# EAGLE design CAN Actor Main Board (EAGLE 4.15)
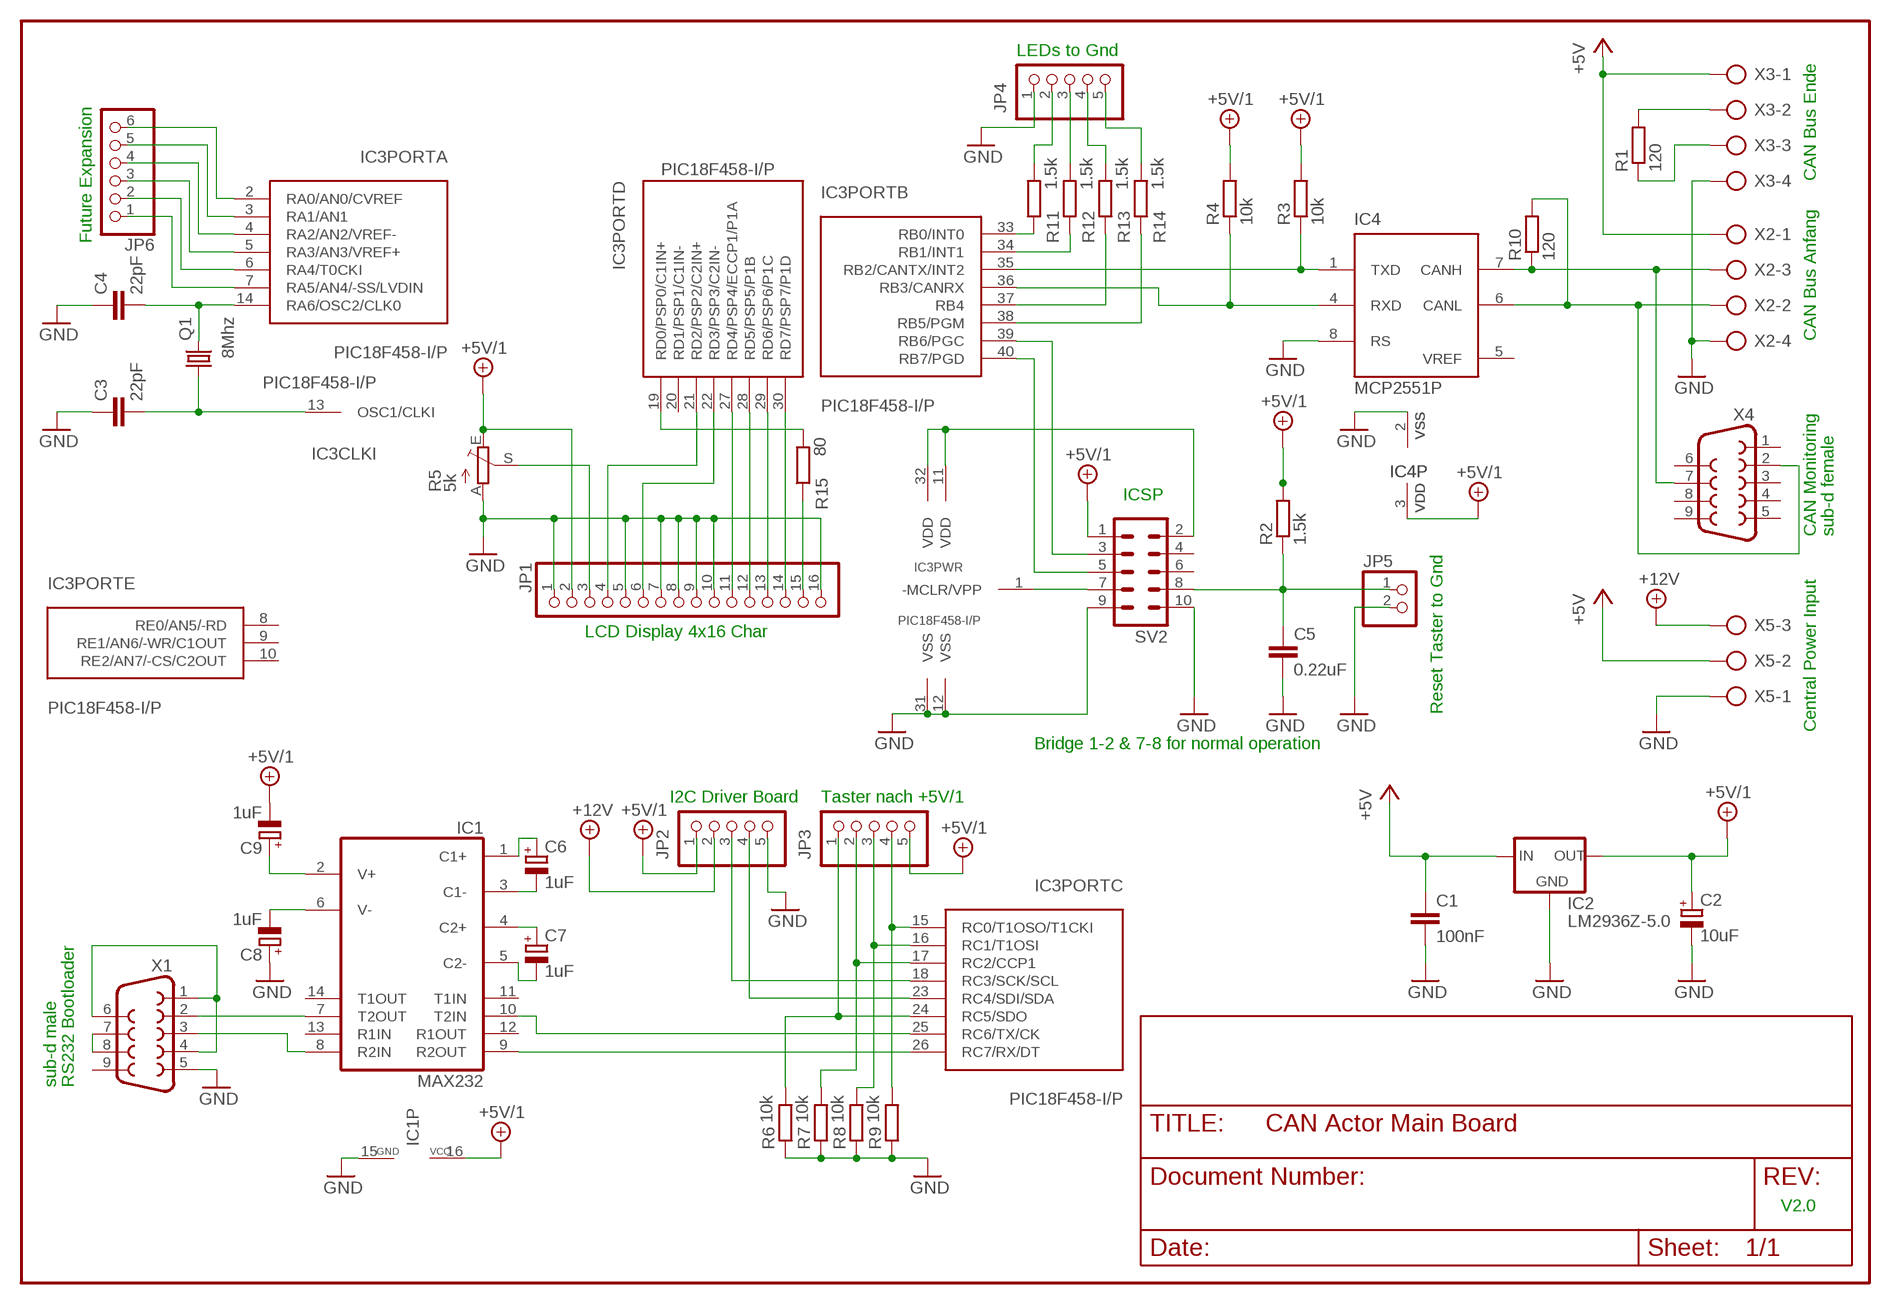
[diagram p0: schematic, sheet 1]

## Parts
C1  100nF  C2.5/2  [C2.5-2]
C2  10uF  CPOL-EUB45181A  [B45181A]
C3  22pF  C-EU025-025X050  [C025-025X050]
C4  22pF  C-EU025-025X050  [C025-025X050]
C5  0.22uF  C-EU025-025X050  [C025-025X050]
C6  1uF  CPOL-EUB45181A  [B45181A]
C7  1uF  CPOL-EUB45181A  [B45181A]
C8  1uF  CPOL-EUB45181A  [B45181A]
C9  1uF  CPOL-EUB45181A  [B45181A]
IC1  MAX232  [DIL16]
IC2  LM2936Z-5.0  78LXX  [78LXX]
IC3  PIC18F458-I/P  [DIL40]
IC4  MCP2551P  [DIL8]
JP1  PINHD-1X16  [1X16]
JP2  PINHD-1X5  [1X05]
JP3  PINHD-1X5  [1X05]
JP4  PINHD-1X5  [1X05]
JP5  PINHD-1X2  [1X02]
JP6  PINHD-1X6  [1X06]
Q1  8Mhz  CRYTALHC49S  [HC49/S]
R1  120  R-EU_0204/7  [0204/7]
R2  1.5k  R-EU_0204/7  [0204/7]
R3  10k  R-EU_0204/7  [0204/7]
R4  10k  R-EU_0204/7  [0204/7]
R5  5k  TRIM_EU-LI10  [LI10]
R6  10k  R-EU_0204/7  [0204/7]
R7  10k  R-EU_0204/7  [0204/7]
R8  10k  R-EU_0204/7  [0204/7]
R9  10k  R-EU_0204/7  [0204/7]
R10  120  R-EU_0204/7  [0204/7]
R11  1.5k  R-EU_0204/7  [0204/7]
R12  1.5k  R-EU_0204/7  [0204/7]
R13  1.5k  R-EU_0204/7  [0204/7]
R14  1.5k  R-EU_0204/7  [0204/7]
R15  80  R-EU_0204/7  [0204/7]
SV2  ML10  [ML10]
X1  F09VB  [F09VB]
X2  AK500/4  [AK500/4]
X3  AK500/4  [AK500/4]
X4  F09VB  [F09VB]
X5  AK500/3  [AK500/3]

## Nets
+5V: C1.1 IC2.IN X2.1 X3.1 X5.2
+5V/1: C2.+ C9.- IC1.16(VCC) IC2.OUT IC4.3(VDD) JP1.2 JP2.1 JP3.5 R2.2 R3.2 R4.2 R5.E SV2.1
+12V: JP2.2 X5.3
GND: C1.2 C2.- C3.1 C4.1 C5.2 C8.+ IC1.15(GND) IC2.GND IC3.12(PWR:VSS) IC3.31(PWR:VSS) IC4.2(VSS) IC4.8(RS) JP1.1 JP1.5 JP1.7 JP1.8 JP1.9 JP1.10 JP1.16 JP2.5 JP4.1 JP5.2 R5.A R6.1 R7.1 R8.1 R9.1 SV2.9 SV2.10 X1.5 X2.4 X3.4 X5.1
N$1: IC3.35(PORTB:RB2/CANTX/INT2) IC4.1(TXD) R3.1
N$2: IC3.36(PORTB:RB3/CANRX) IC4.4(RXD) R4.1
N$3: IC4.7(CANH) R10.1 X2.3 X4.7
N$4: C3.2 IC3.13(CLKI:OSC1/CLKI) Q1.1
N$5: IC4.6(CANL) R10.2 X2.2 X4.2
N$6: IC3.1(PWR:-MCLR/VPP) SV2.7
N$7: IC3.11(PWR:VDD) IC3.32(PWR:VDD) SV2.2
N$8: IC3.39(PORTB:RB6/PGC) SV2.3
N$9: C4.2 IC3.14(PORTA:RA6/OSC2/CLK0) Q1.2
N$10: IC3.33(PORTB:RB0/INT0) R11.1
N$11: IC3.34(PORTB:RB1/INT1) R12.1
N$12: IC3.40(PORTB:RB7/PGD) SV2.5
N$13: IC3.27(PORTD:RD4/PSP4/ECCP1/P1A) JP1.11
N$14: C5.1 JP5.1 R2.1 SV2.8
N$15: IC3.22(PORTD:RD3/PSP3/C2IN-) JP1.6
N$16: JP1.3 R5.S
N$17: IC3.21(PORTD:RD2/PSP2/C2IN+) JP1.4
N$18: IC3.30(PORTD:RD7/PSP7/P1D) JP1.14
N$19: IC3.29(PORTD:RD6/PSP6/P1C) JP1.13
N$20: IC3.28(PORTD:RD5/PSP5/P1B) JP1.12
N$21: IC1.10(T2IN) IC3.25(PORTC:RC6/TX/CK)
N$22: IC1.9(R2OUT) IC3.26(PORTC:RC7/RX/DT)
N$23: C6.- IC1.3(C1-)
N$24: C6.+ IC1.1(C1+)
N$25: C7.+ IC1.4(C2+)
N$26: C7.- IC1.5(C2-)
N$27: C8.- IC1.6(V-)
N$28: C9.+ IC1.2(V+)
N$29: IC1.7(T2OUT) X1.2
N$30: IC1.8(R2IN) X1.3
N$31: X1.7 X1.8
N$32: X1.1 X1.4 X1.6
N$33: IC3.18(PORTC:RC3/SCK/SCL) JP2.3
N$34: IC3.23(PORTC:RC4/SDI/SDA) JP2.4
N$35: IC3.15(PORTC:RC0/T1OSO/T1CKI) JP3.4 R9.2
N$36: IC3.16(PORTC:RC1/T1OSI) JP3.3 R8.2
N$37: IC3.17(PORTC:RC2/CCP1) JP3.2 R7.2
N$38: IC3.24(PORTC:RC5/SDO) JP3.1 R6.2
N$39: IC3.37(PORTB:RB4) R13.1
N$40: R1.2 X3.2
N$41: R1.1 X3.3
N$42: IC3.38(PORTB:RB5/PGM) R14.1
N$43: JP4.2 R11.2
N$44: JP4.3 R12.2
N$45: JP4.4 R13.2
N$46: JP4.5 R14.2
N$48: JP1.15 R15.1
N$49: IC3.19(PORTD:RD0/PSP0/C1IN+) R15.2
N$50: IC3.7(PORTA:RA5/AN4/-SS/LVDIN) JP6.1
N$51: IC3.6(PORTA:RA4/T0CKI) JP6.2
N$52: IC3.5(PORTA:RA3/AN3/VREF+) JP6.3
N$53: IC3.4(PORTA:RA2/AN2/VREF-) JP6.4
N$54: IC3.3(PORTA:RA1/AN1) JP6.5
N$55: IC3.2(PORTA:RA0/AN0/CVREF) JP6.6
Unconnected: IC1.11(T1IN) IC1.12(R1OUT) IC1.13(R1IN) IC1.14(T1OUT) IC3.8(PORTE:RE0/AN5/-RD) IC3.9(PORTE:RE1/AN6/-WR/C1OUT) IC3.10(PORTE:RE2/AN7/-CS/C2OUT) IC3.20(PORTD:RD1/PSP1/C1IN-) SV2.4 SV2.6 X1.9 X4.1 X4.3 X4.4 X4.5 X4.6 X4.8 X4.9

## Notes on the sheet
- LEDs to Gnd
- CAN Bus Ende
- Future Expansion
- CAN Bus Anfang
- ICSP
- CAN Monitoring | sub-d female
- LCD Display 4x16 Char
- Reset Taster to Gnd
- Central Power Input
- Bridge 1-2 & 7-8 for normal operation
- I2C Driver Board | Taster nach +5V/1
- sub-d male | RS232 Bootloader
- V2.0

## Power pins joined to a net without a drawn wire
VREF: IC4.5(VREF)

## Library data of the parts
C1 = capacitor-wima:C: CAPACITOR
C2 C6-C9 = rcl:CPOL-EU: POLARIZED CAPACITOR, European symbol
C3-C5 = rcl:C-EU: CAPACITOR, European symbol
IC1 = maxim:MAX232: RS232 TRANSEIVER
IC2 = v-reg:78LXX: VOLTAGE REGULATOR
IC3 = pic18fxx20-fxx8:PIC18F4*8: 40-Pin High Performance, Enhanced FLASH Microcontrollers with CAN device program memory (bytes) data RAM (bytes) PIC18F44816K768 PIC18F45832K1536
IC4 = microchip_can:MCP2551: High Speed CAN tranceiver
JP1 = pinhead:PINHD-1X16: PIN HEADER
JP2-JP4 = pinhead:PINHD-1X5: PIN HEADER
JP5 = pinhead:PINHD-1X2: PIN HEADER
JP6 = pinhead:PINHD-1X6: PIN HEADER
Q1 = crystal:CRYTAL: CRYSTAL
R1-R4 R6-R15 = rcl:R-EU_: RESISTOR, European symbol
R5 = pot:TRIM_EU-: POTENTIOMETER
SV2 = con-harting-ml:ML10: HARTING
X1 X4 = con-subd:F09: SUB-D
X2 X3 = con-ptr500:AK500/4: CONNECTOR
X5 = con-ptr500:AK500/3: CONNECTOR

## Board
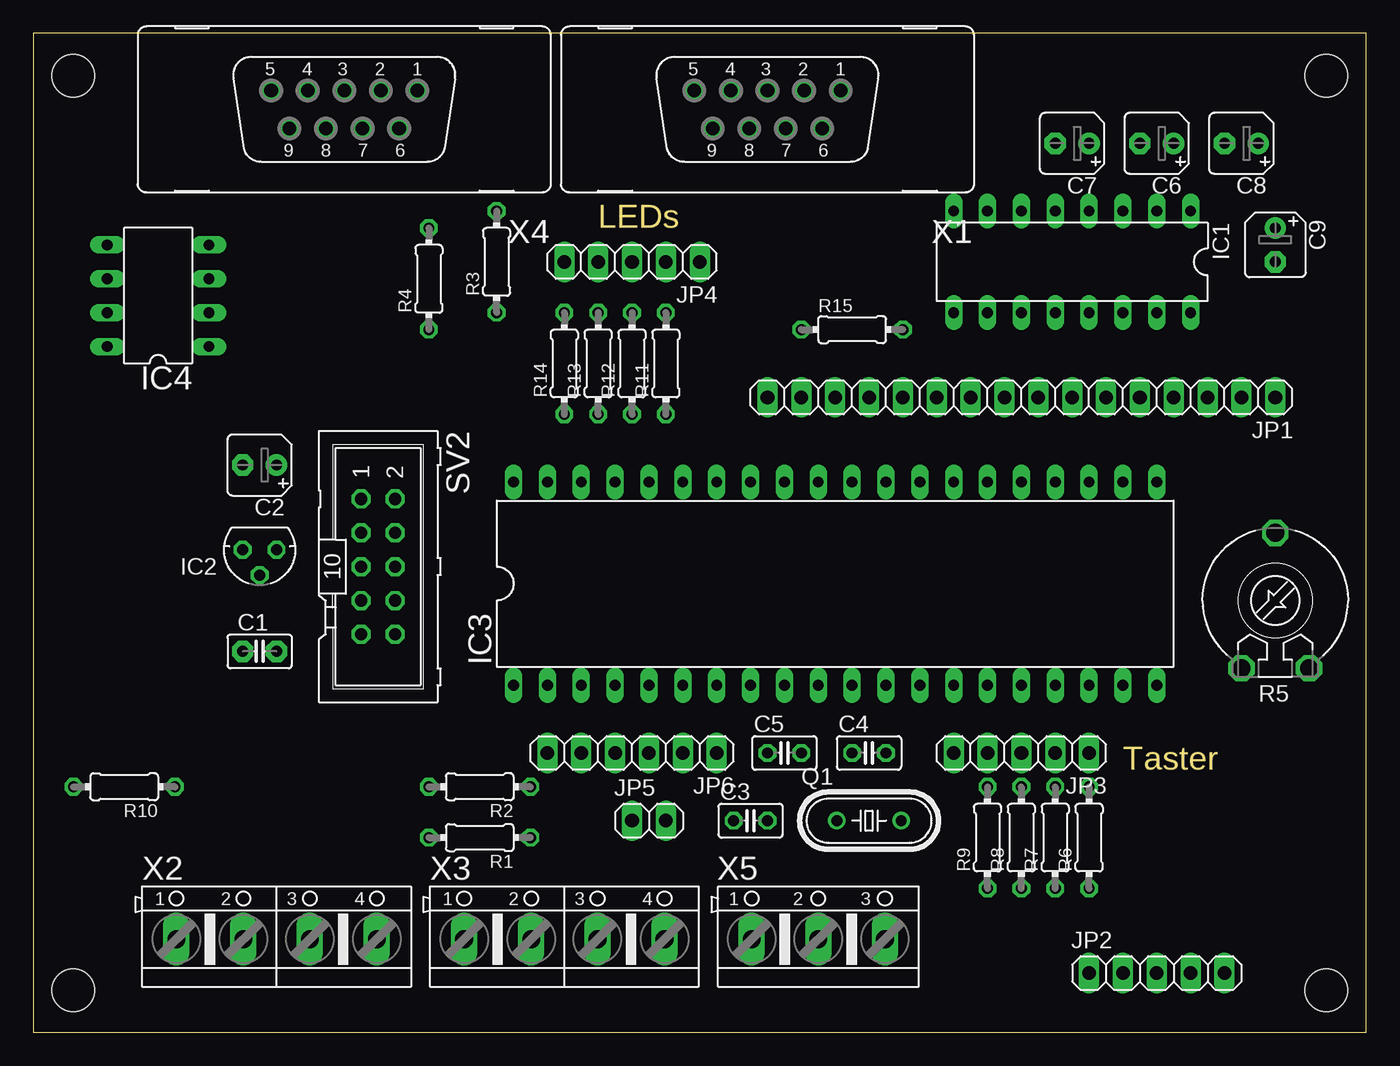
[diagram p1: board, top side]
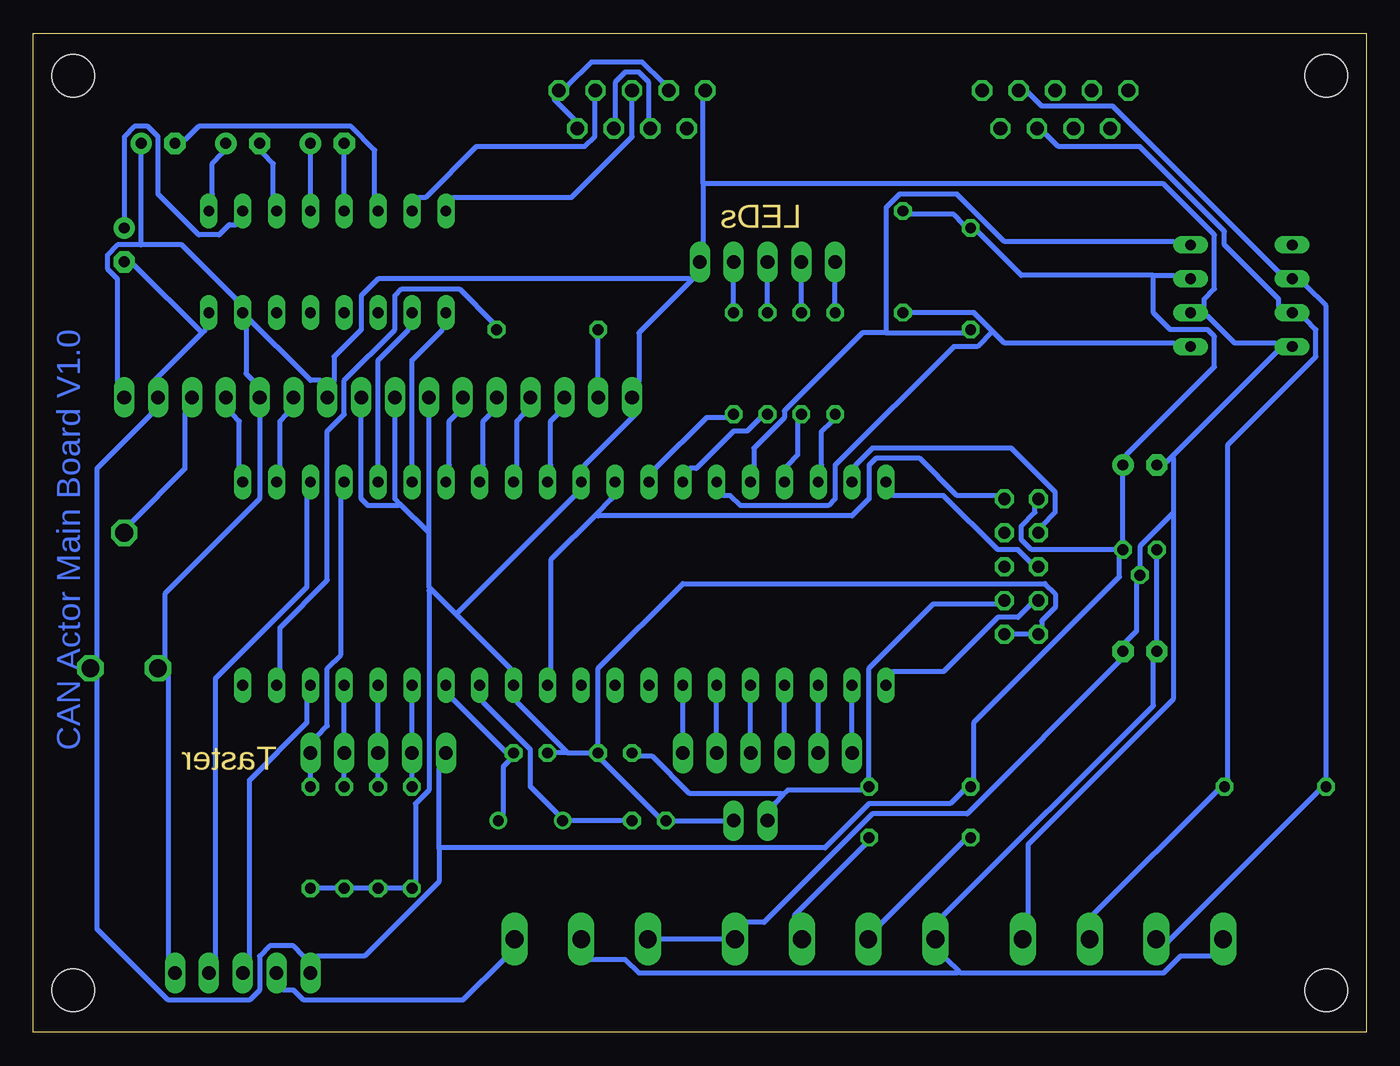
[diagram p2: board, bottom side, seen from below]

Size 100 x 74.92 mm. Coordinates in mm from the lower left corner, seen from the top.
Outline: 0,0 100,0 100,74.92 0,74.92 0,0
Copper layers (1*16): Top 0.035mm / dielectric 1.5mm / Bottom 0.035mm
Design rules "default": minimum track width 15mil, minimum drill 24mil, track to track 8mil, track to pad 8mil, pad to pad 8mil, via to via 8mil, smd to smd 8mil, copper to edge 40mil, drill to drill 8mil, minimum pad ring 10mil, minimum via ring 8mil, stop-mask expansion 4mil, vias tented up to drill 0mil, thermal gap 10mil
Holes 3.2 mm at 3.01,3.17 3.01,71.75 96.99,71.75 96.99,3.17

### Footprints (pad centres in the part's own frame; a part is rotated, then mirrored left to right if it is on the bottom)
C2.5-2 = drill 0.813 pad 1.6 octagon: 1 -1.27,0; 2 1.27,0
B45181A = drill 0.813 pad 1.6 round: + -1.27,0 | drill 0.813 pad 1.6 octagon: - 1.27,0
C025-025X050 = drill 0.813 octagon: 1 -1.27,0; 2 1.27,0
DIL16 = drill 0.813 long: 1 -8.89,-3.81; 2 -6.35,-3.81; 3 -3.81,-3.81; 4 -1.27,-3.81; 5 1.27,-3.81; 6 3.81,-3.81; 7 6.35,-3.81; 8 8.89,-3.81; 9 8.89,3.81; 10 6.35,3.81; 11 3.81,3.81; 12 1.27,3.81; 13 -1.27,3.81; 14 -3.81,3.81; 15 -6.35,3.81; 16 -8.89,3.81
78LXX = drill 0.813 octagon: GND 0,1.905; IN 1.27,0; OUT -1.27,0
DIL40 = drill 0.813 long: 1 -24.13,-7.62; 2 -21.59,-7.62; 3 -19.05,-7.62; 4 -16.51,-7.62; 5 -13.97,-7.62; 6 -11.43,-7.62; 7 -8.89,-7.62; 8 -6.35,-7.62; 9 -3.81,-7.62; 10 -1.27,-7.62; 11 1.27,-7.62; 12 3.81,-7.62; 13 6.35,-7.62; 14 8.89,-7.62; 15 11.43,-7.62; 16 13.97,-7.62; 17 16.51,-7.62; 18 19.05,-7.62; 19 21.59,-7.62; 20 24.13,-7.62; 21 24.13,7.62; 22 21.59,7.62; 23 19.05,7.62; 24 16.51,7.62; 25 13.97,7.62; 26 11.43,7.62; 27 8.89,7.62; 28 6.35,7.62; 29 3.81,7.62; 30 1.27,7.62; 31 -1.27,7.62; 32 -3.81,7.62; 33 -6.35,7.62; 34 -8.89,7.62; 35 -11.43,7.62; 36 -13.97,7.62; 37 -16.51,7.62; 38 -19.05,7.62; 39 -21.59,7.62; 40 -24.13,7.62
DIL8 = drill 0.813 long: 1 -3.81,-3.81; 2 -1.27,-3.81; 3 1.27,-3.81; 4 3.81,-3.81; 5 3.81,3.81; 6 1.27,3.81; 7 -1.27,3.81; 8 -3.81,3.81
1X16 = drill 1.016 long: 1 -19.05,0; 2 -16.51,0; 3 -13.97,0; 4 -11.43,0; 5 -8.89,0; 6 -6.35,0; 7 -3.81,0; 8 -1.27,0; 9 1.27,0; 10 3.81,0; 11 6.35,0; 12 8.89,0; 13 11.43,0; 14 13.97,0; 15 16.51,0; 16 19.05,0
1X05 = drill 1.016 long: 1 -5.08,0; 2 -2.54,0; 3 0,0; 4 2.54,0; 5 5.08,0
1X02 = drill 1.016 long: 1 -1.27,0; 2 1.27,0
1X06 = drill 1.016 long: 1 -6.35,0; 2 -3.81,0; 3 -1.27,0; 4 1.27,0; 5 3.81,0; 6 6.35,0
HC49/S = drill 0.813 round: 1 -2.413,0; 2 2.413,0
0204/7 = drill 0.813 octagon: 1 -3.81,0; 2 3.81,0
LI10 = drill 1.321 octagon: A -2.54,-5.08; E 2.54,-5.08; S 0,5.08
ML10 = drill 0.914 octagon: 1 -5.08,-1.27; 2 -5.08,1.27; 3 -2.54,-1.27; 4 -2.54,1.27; 5 0,-1.27; 6 0,1.27; 7 2.54,-1.27; 8 2.54,1.27; 9 5.08,-1.27; 10 5.08,1.27
F09VB = drill 1.016 octagon: 1 -5.486,-1.422; 2 -2.743,-1.422; 3 0,-1.422; 4 2.743,-1.422; 5 5.486,-1.422; 6 -4.115,1.422; 7 -1.372,1.422; 8 1.372,1.422; 9 4.115,1.422
AK500/4 = drill 1.321 long: 1 -7.518,0; 2 -2.489,0; 3 2.489,0; 4 7.518,0
AK500/3 = drill 1.321 long: 1 -5.004,0; 2 0,0; 3 5.004,0

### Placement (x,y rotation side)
C1  16.98,28.57 0 top
C2  16.98,42.54 180 top
C3  53.81,15.87 0 top
C4  62.7,20.95 0 top
C5  56.35,20.95 0 top
C6  84.29,66.67 180 top
C7  77.94,66.67 180 top
C8  90.64,66.67 180 top
C9  93.18,59.05 270 top
IC1  77.94,57.78 180 top
IC2  16.98,36.19 180 top
IC3  60.16,33.65 0 top
IC4  9.36,55.24 90 top
JP1  74.13,47.62 180 top
JP2  84.29,4.44 0 top
JP3  74.13,20.95 180 top
JP4  44.92,57.78 180 top
JP5  46.19,15.87 0 top
JP6  44.92,20.95 180 top
Q1  62.7,15.87 0 top
R1  33.49,14.6 180 top
R2  33.49,18.41 180 top
R3  34.76,57.78 90 top
R4  29.68,56.51 90 top
R5  93.18,32.38 0 top
R6  79.21,14.6 90 top
R7  76.67,14.6 90 top
R8  74.13,14.6 90 top
R9  71.59,14.6 90 top
R10  6.82,18.41 180 top
R11  47.46,50.16 90 top
R12  44.92,50.16 90 top
R13  42.38,50.16 90 top
R14  39.84,50.16 90 top
R15  61.43,52.7 0 top
SV2  25.87,34.92 270 top
X1  55.08,69.21 180 top
X2  18.25,6.98 0 top
X3  39.84,6.98 0 top
X4  23.33,69.21 180 top
X5  58.89,6.98 0 top

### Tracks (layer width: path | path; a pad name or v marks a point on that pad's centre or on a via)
+5V
  Bottom 0.381: IC2.IN C1.1 15.96,27.81 15.96,24.51 31.71,8.76 X3.1 31.46,5.46 30.57,4.57 | 30.57,4.57 30.44,4.44 15.2,4.44 13.93,5.71 11.65,5.71 X2.1 | X5.2 58.13,5.46 55.59,5.46 54.57,4.44 30.7,4.44 30.57,4.57
+5V/1
  Bottom 0.381: 87.34,52.45 90.89,48.89 JP1.2 91.15,46.35 95.21,42.29 95.21,28.06 R5.E 95.21,26.54 95.21,7.74 89.88,2.41 83.78,2.41 83.02,3.17 83.02,5.71 82.26,6.47 80.48,6.47 79.72,5.71 JP2.1 78.7,5.71 75.15,5.71 69.56,11.3 69.56,13.84 | 87.34,52.45 87.08,52.7 IC1.16 | 87.34,52.45 92.42,57.53 C9.- | 69.56,13.84 69.56,19.68 JP3.5 | 15.96,56.76 25.87,56.76 29.17,60.07 R4.2 30.19,60.57 30.95,61.34 34.25,61.34 R3.2 | 15.96,56.76 14.44,56.76 IC4.3 | IC2.OUT C2.+ 18,43.3 11.39,49.91 11.39,52.19 11.9,52.7 14.69,52.7 15.96,53.97 15.96,56.76 | IC2.OUT 18.5,35.68 18.5,34.16 29.43,23.24 29.43,18.92 R2.2 30.19,18.16 31.2,17.14 37.3,17.14 40.6,13.84 69.56,13.84 | SV2.1 24.85,39.49 24.85,38.98 25.87,37.97 25.87,36.95 25.11,36.19 IC2.OUT
+12V
  Bottom 0.381: JP2.2 81.24,3.17 80.48,3.17 79.72,2.41 67.78,2.41 64.73,5.46 X5.3
GND
  Bottom 0.381: X5.1 X3.4 46.44,8.25 45.17,8.25 37.05,16.38 29.93,16.38 18.5,27.81 C1.2 18,29.33 17.23,30.09 17.23,33.65 IC2.GND 16.98,36.44 14.44,38.98 | 14.57,43.17 6.57,51.18 IC4.8 6.82,51.68 9.87,51.68 11.9,53.72 IC4.2 12.15,54.48 12.15,54.99 11.39,55.75 11.39,59.81 15.2,63.62 49.75,63.62 | 14.57,43.17 14.95,42.79 C2.- | 14.44,38.98 14.44,43.05 14.57,43.17 | 14.44,38.98 14.44,25.01 25.36,14.09 25.36,8.76 X2.4 | JP2.5 89.88,5.71 89.88,26.79 R5.A 90.13,28.06 90.13,32.89 83.02,40 JP1.5 83.53,48.89 84.04,49.4 84.04,52.7 IC1.15 | IC1.15 79.21,48.89 78.45,48.89 JP1.7 77.43,48.89 77.43,50.67 75.4,52.7 75.4,55.24 74.13,56.51 50.76,56.51 50.63,56.38 | 91.91,59.05 88.86,59.05 84.8,54.99 IC1.15 | 91.91,59.05 93.69,59.05 94.45,58.29 94.45,57.27 93.69,56.51 93.69,48.89 JP1.1 | 91.91,59.05 C8.+ | 49.75,63.62 49.75,69.97 X1.5 | 49.75,63.62 49.75,59.05 JP4.1 50.51,56.51 50.63,56.38 | 50.63,56.38 54.57,52.45 54.57,48.89 JP1.16 54.83,46.35 58.64,42.54 IC3.31 59.4,40.25 68.29,31.36 | R6.1 R7.1 R8.1 R9.1 71.34,11.3 71.34,17.14 70.32,18.16 70.32,33.14 70.19,33.27 | JP5.2 C3.1 53.05,16.12 57.37,20.44 C5.2 | SV2.10 SV2.9 24.35,30.35 24.35,30.86 23.33,31.87 23.33,32.89 24.09,33.65 51.27,33.65 57.62,27.3 C5.2 | 59.91,20.95 C5.2 | 59.91,20.95 C4.1 | 59.91,20.95 63.72,24.76 IC3.12 64.22,27.3 68.29,31.36 | 70.32,37.46 70.32,33.4 70.19,33.27 | 68.29,31.36 70.19,33.27 | 70.32,37.46 JP1.10 | 70.32,37.46 72.48,39.62 | 72.48,39.62 72.86,40 JP1.9 | JP1.8 75.4,40 74.89,39.49 72.61,39.49 72.48,39.62
N$1
  Bottom 0.381: 28.03,52.57 29.43,53.97 R3.1 | 28.03,52.57 27.14,51.68 14.44,51.68 IC4.1 | IC3.35 48.22,40.25 47.71,40.25 46.95,39.49 40.35,39.49 39.84,40 39.84,42.54 30.95,51.43 29.17,51.43 28.03,52.57
N$2
  Bottom 0.381: 36.03,52.45 30.19,52.45 R4.1 | 36.03,52.45 37.81,52.45 43.65,46.6 43.65,46.1 45.94,43.81 45.94,42.54 IC3.36 | 36.03,52.45 36.03,61.84 35.01,62.86 30.7,62.86 27.14,59.3 14.44,59.3 IC4.4
N$3
  Bottom 0.381: X2.3 20.54,8.76 11.14,18.16 R10.1 10.38,18.92 10.38,44.06 3.77,50.67 3.77,52.7 4.53,53.46 IC4.7 6.57,54.48 6.57,54.99 10.63,59.05 10.63,60.07 16.98,66.42 23.08,66.42 24.09,67.43 X4.7
N$4
  Bottom 0.381: C3.2 Q1.1 60.67,16.38 62.7,18.41 62.7,21.2 66.26,24.76 IC3.13
N$5
  Bottom 0.381: X2.2 14.95,6.73 3.52,18.16 R10.2 3.01,54.48 4.53,56 IC4.6 6.57,57.02 19.01,69.46 24.35,69.46 25.36,70.48 X4.2
N$6
  Bottom 0.381: IC3.1 35.52,27.05 31.71,27.05 27.65,31.11 26.12,31.11 25.11,32.13 SV2.7
N$7
  Bottom 0.381: 57.75,38.86 56.6,40 IC3.32 | 57.75,38.86 61.18,35.43 61.18,27.3 IC3.11 | SV2.2 27.65,40.25 30.7,40.25 33.49,43.05 36.79,43.05 37.3,42.54 37.3,40 38.57,38.73 57.62,38.73 57.75,38.86
N$8
  Bottom 0.381: IC3.39 38.32,42.54 37.05,43.81 26.63,43.81 23.33,40.51 23.33,38.98 24.35,37.97 SV2.3
N$9
  Bottom 0.381: Q1.2 64.73,16.38 64.73,19.93 64.22,20.44 C4.2 64.48,20.95 68.54,25.01 IC3.14
N$10
  Bottom 0.381: R11.1 47.97,46.1 49.49,46.1 53.3,42.29 IC3.33
N$11
  Bottom 0.381: IC3.34 50.76,42.29 50.25,42.29 47.46,45.08 46.44,45.08 45.43,46.1 R12.1
N$12
  Bottom 0.381: IC3.40 35.52,40.25 31.71,40.25 27.65,36.19 26.12,36.19 25.11,35.17 SV2.5
N$13
  Bottom 0.381: IC3.27 68.8,42.54 68.8,45.84 68.29,46.35 JP1.11
N$14
  Bottom 0.381: 43.78,17.77 44.41,17.14 JP5.1 | 43.78,17.77 43.4,18.16 37.81,18.16 R2.1 37.3,27.3 32.47,32.13 27.65,32.13 SV2.8 | C5.1 54.57,20.7 53.56,20.7 50.76,17.9 43.9,17.9 43.78,17.77
N$15
  Bottom 0.381: IC3.22 81.5,42.54 81.5,45.84 80.99,46.35 JP1.6
N$16
  Bottom 0.381: JP1.3 88.61,46.35 88.61,42.29 92.67,38.22 R5.S
N$17
  Bottom 0.381: IC3.21 84.54,42.54 84.54,45.84 85.05,46.35 JP1.4
N$18
  Bottom 0.381: IC3.30 61.18,42.54 61.18,45.84 60.67,46.35 JP1.14
N$19
  Bottom 0.381: IC3.29 63.72,42.54 63.72,45.84 63.21,46.35 JP1.13
N$20
  Bottom 0.381: IC3.28 66.26,42.54 66.26,45.84 65.75,46.35 JP1.12
N$21
  Bottom 0.381: IC3.25 74.13,50.41 71.84,52.7 IC1.10
N$22
  Bottom 0.381: IC3.26 71.59,50.41 69.3,52.7 IC1.9
N$23
  Bottom 0.381: IC1.3 82,62.86 82,65.15 82.77,65.91 C6.-
N$24
  Bottom 0.381: IC1.1 86.58,62.86 86.58,65.15 85.81,65.91 C6.+
N$25
  Bottom 0.381: IC1.4 C7.+
N$26
  Bottom 0.381: IC1.5 C7.-
N$27
  Bottom 0.381: IC1.6 74.38,62.86 74.38,66.16 76.16,67.94 87.59,67.94 88.61,66.92 C8.-
N$28
  Bottom 0.381: IC1.2 84.8,60.57 85.31,60.57 86.07,59.81 87.59,59.81 90.64,62.86 90.64,67.18 91.4,67.94 92.42,67.94 93.18,67.18 C9.+
N$29
  Bottom 0.381: IC1.7 71.08,62.61 70.57,62.61 66.76,66.42 58.64,66.42 57.87,67.18 57.87,69.97 X1.2
N$30
  Bottom 0.381: IC1.8 68.54,62.61 59.65,62.61 55.08,67.18 X1.3
N$31
  Bottom 0.381: X1.8 53.81,68.45 53.81,71.24 54.57,72 55.59,72 56.35,71.24 56.35,68.45 X1.7
N$32
  Bottom 0.381: X1.4 52.79,71.24 54.32,72.77 58.13,72.77 59.91,70.99 X1.1 60.92,69.97 59.4,68.45 X1.6
N$33
  Bottom 0.381: IC3.18 79.46,24.76 79.46,23.24 83.78,18.92 83.78,5.71 JP2.3
N$34
  Bottom 0.381: IC3.23 79.46,40 79.46,33.4 86.32,26.54 86.32,5.71 JP2.4
N$35
  Bottom 0.381: R9.2 JP3.4 IC3.15
N$36
  Bottom 0.381: R8.2 JP3.3 IC3.16
N$37
  Bottom 0.381: R7.2 JP3.2 IC3.17
N$38
  Bottom 0.381: R6.2 JP3.1 78.7,22.22 77.94,22.98 77.94,27.3 76.92,28.32 76.92,40 IC3.24
N$39
  Bottom 0.381: R13.1 42.63,45.84 42.63,43.3 43.4,42.54 IC3.37
N$40
  Bottom 0.381: R1.2 30.19,14.35 36.54,8 X3.2
N$41
  Bottom 0.381: R1.1 37.55,14.09 42.89,8.76 X3.3
N$42
  Bottom 0.381: IC3.38 40.86,42.54 40.86,45.08 40.09,45.84 R14.1
N$43
  Bottom 0.381: R11.2 JP4.2
N$44
  Bottom 0.381: R12.2 JP4.3
N$45
  Bottom 0.381: R13.2 JP4.4
N$46
  Bottom 0.381: R14.2 JP4.5
N$48
  Bottom 0.381: JP1.15 R15.1
N$49
  Bottom 0.381: IC3.19 81.5,27.3 81.5,30.35 77.94,33.9 77.94,45.08 76.67,46.35 76.67,48.89 72.86,52.7 72.86,55.24 72.35,55.75 68.03,55.75 65.49,53.21 R15.2
N$50
  Bottom 0.381: JP6.1 IC3.7
N$51
  Bottom 0.381: JP6.2 IC3.6
N$52
  Bottom 0.381: JP6.3 IC3.5
N$53
  Bottom 0.381: JP6.4 IC3.4
N$54
  Bottom 0.381: JP6.5 IC3.3
N$55
  Bottom 0.381: JP6.6 IC3.2

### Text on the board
Bottom: CAN Actor Main Board V1.0
Dimension: LEDs | Taster
tOrigins: CAN Actor Main Board | +5V Lo Hi Gnd | +5V Lo Hi Gnd | Gnd +5V +12V | +5V +12V SCL SDA Gnd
